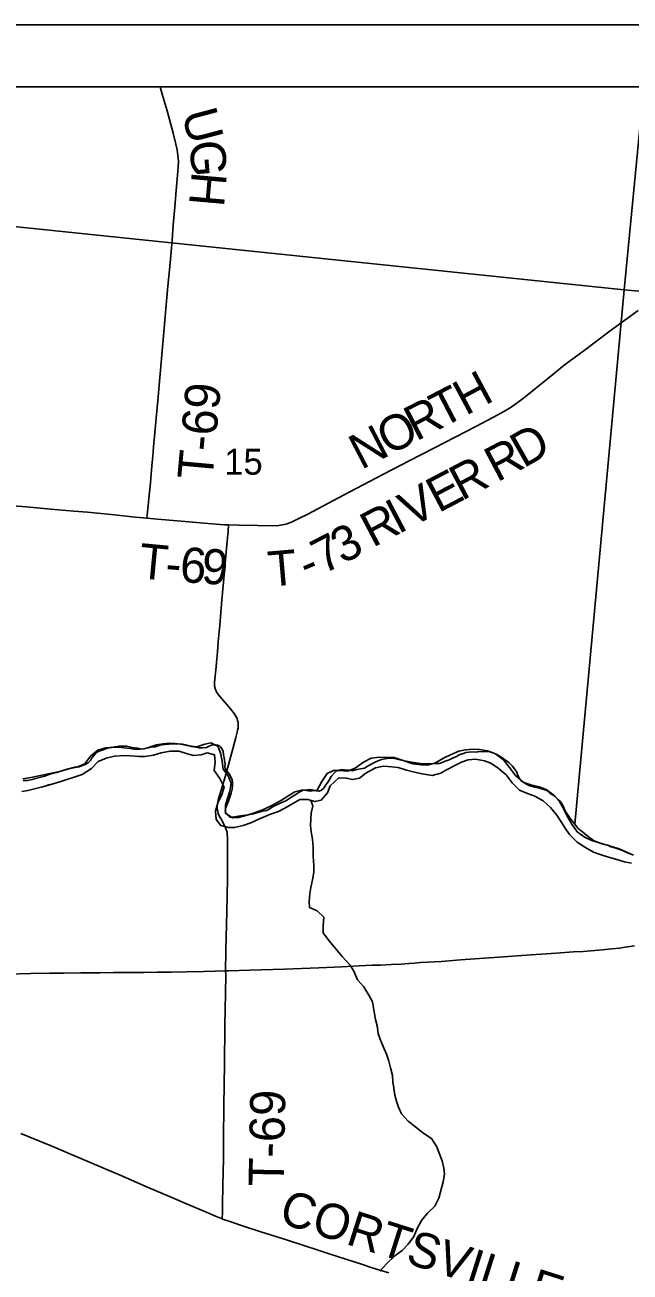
# Model space of a CAD drawing. Extents: x -19.5 to 44.1, y 0 to 22.
# Drawn here: x -15.704 to -14.727, y 7.445 to 9.461 of the extents above; entities that cross this region are included whole.
import ezdxf

# ---------------------------------------------------------------- set-up
doc = ezdxf.new("R2010")
doc.units = 0
for name, color, linetype in [('GM_X_Major_River', 7, 'Continuous'), ('GM_X_Minor_River', 7, 'Continuous'), ('GM_X_Section', 7, 'Continuous'), ('GM_X_Section_Text', 7, 'Continuous'), ('GM_X_Township_Road', 7, 'Continuous'), ('GM_X_Township_Road_Text', 7, 'Continuous'), ('SH_Data', 7, 'Continuous')]:
    doc.layers.add(name, color=color, linetype=linetype)

msp = doc.modelspace()

# ---------------------------------------------------------------- linework, layer by layer
at = {"layer": 'GM_X_Major_River'}
for points in [[(-14.7209, 8.1187), (-14.7337, 8.1239), (-14.7442, 8.1287), (-14.7597, 8.1339), (-14.7729, 8.1376), (-14.7884, 8.1425), (-14.7993, 8.1472), (-14.812, 8.1566), (-14.8209, 8.1686), (-14.8282, 8.1816), (-14.8333, 8.192), (-14.8407, 8.2054), (-14.8496, 8.2155), (-14.8623, 8.2249), (-14.8733, 8.2289), (-14.8872, 8.2322), (-14.8993, 8.2366), (-14.9116, 8.2475), (-14.9212, 8.2602), (-14.9313, 8.2726), (-14.9443, 8.2827), (-14.9572, 8.2875), (-14.97, 8.2893), (-14.9803, 8.2899), (-14.9924, 8.289), (-15.0031, 8.2869), (-15.0157, 8.2814), (-15.028, 8.2752), (-15.041, 8.2679), (-15.054, 8.2643), (-15.0642, 8.2645), (-15.0775, 8.2663), (-15.0933, 8.2719), (-15.1076, 8.2764), (-15.1319, 8.2769), (-15.1452, 8.2756), (-15.1575, 8.269), (-15.171, 8.2594), (-15.1832, 8.2543), (-15.1965, 8.2553), (-15.206, 8.2555), (-15.2159, 8.2508), (-15.2245, 8.2376), (-15.232, 8.2237), (-15.2442, 8.2221), (-15.2555, 8.2242), (-15.2681, 8.221), (-15.2781, 8.2151), (-15.29, 8.2078), (-15.3042, 8.1993), (-15.3191, 8.1927), (-15.3336, 8.1873), (-15.3451, 8.1834), (-15.3592, 8.1795), (-15.3691, 8.1789), (-15.3803, 8.1863), (-15.3804, 8.2), (-15.3764, 8.2121), (-15.3732, 8.2223), (-15.3711, 8.2348), (-15.3765, 8.2482), (-15.3843, 8.2579), (-15.3859, 8.2701), (-15.3876, 8.2819), (-15.3923, 8.2941), (-15.404, 8.3001), (-15.4135, 8.298), (-15.4265, 8.294), (-15.4394, 8.2954), (-15.4526, 8.2983), (-15.4621, 8.2993), (-15.4715, 8.2995), (-15.4818, 8.2985), (-15.4917, 8.2968), (-15.5016, 8.294), (-15.5119, 8.2904), (-15.5245, 8.2895), (-15.5343, 8.2912), (-15.5487, 8.2926), (-15.5608, 8.2932), (-15.5734, 8.2923), (-15.5867, 8.2884), (-15.5983, 8.2788), (-15.6073, 8.2664), (-15.6203, 8.261), (-15.6347, 8.2582), (-15.6466, 8.2546), (-15.6561, 8.2525), (-15.6687, 8.2498), (-15.6946, 8.2442), (-15.7079, 8.2422)], [(-14.7245, 8.1055), (-14.7355, 8.108), (-14.7483, 8.1117), (-14.7616, 8.1153), (-14.7732, 8.1194), (-14.7857, 8.1234), (-14.8, 8.1313), (-14.8123, 8.1399), (-14.8246, 8.1519), (-14.8316, 8.1623), (-14.8379, 8.1727), (-14.8449, 8.1831), (-14.8553, 8.1958), (-14.8668, 8.2067), (-14.8804, 8.2142), (-14.8921, 8.2182), (-14.9052, 8.2238), (-14.9171, 8.2358), (-14.9268, 8.2485), (-14.9395, 8.2594), (-14.9518, 8.2673), (-14.962, 8.2713), (-14.9764, 8.2738), (-14.9882, 8.2729), (-14.9989, 8.2689), (-15.0088, 8.2642), (-15.023, 8.2565), (-15.0326, 8.251), (-15.0463, 8.2475), (-15.0626, 8.25), (-15.0747, 8.2526), (-15.0879, 8.2562), (-15.1015, 8.2603), (-15.1117, 8.2617), (-15.125, 8.2623), (-15.1379, 8.2599), (-15.1533, 8.2514), (-15.1637, 8.2433), (-15.1751, 8.2408), (-15.1853, 8.2433), (-15.1974, 8.2439), (-15.211, 8.2305), (-15.2157, 8.2196), (-15.2258, 8.2076), (-15.2358, 8.2052), (-15.2474, 8.2088), (-15.26, 8.2087), (-15.273, 8.201), (-15.2853, 8.194), (-15.2949, 8.1892), (-15.3075, 8.1849), (-15.3266, 8.1769), (-15.3392, 8.1711), (-15.3515, 8.1664), (-15.3656, 8.1636), (-15.3755, 8.1631), (-15.3879, 8.1667), (-15.3953, 8.1764), (-15.3966, 8.1897), (-15.3925, 8.2033), (-15.3862, 8.2169), (-15.3826, 8.2286), (-15.3895, 8.2424), (-15.3984, 8.2555), (-15.397, 8.2691), (-15.3979, 8.2809), (-15.41, 8.2842), (-15.4195, 8.2806), (-15.4321, 8.2797), (-15.4419, 8.2822), (-15.4558, 8.2866), (-15.4699, 8.2869), (-15.484, 8.2841), (-15.4966, 8.2802), (-15.5103, 8.2782), (-15.5198, 8.2784), (-15.5338, 8.2794), (-15.544, 8.28), (-15.5596, 8.2788), (-15.5733, 8.2752), (-15.586, 8.2698), (-15.5968, 8.2586), (-15.6118, 8.249), (-15.6263, 8.244), (-15.6366, 8.2411), (-15.6465, 8.2375), (-15.6626, 8.2329), (-15.6759, 8.229), (-15.6866, 8.2262), (-15.6996, 8.223), (-15.7095, 8.2213)]]:
    msp.add_lwpolyline(points, dxfattribs=at)
at = {"layer": 'GM_X_Minor_River'}
for points in [[(-15.6682, 8.2316), (-15.6642, 8.2327)], [(-15.2422, 8.2072), (-15.2394, 8.1986), (-15.2418, 8.1865), (-15.2426, 8.1766), (-15.2431, 8.1664), (-15.2421, 8.1565), (-15.2395, 8.1443), (-15.2385, 8.1318), (-15.2387, 8.117), (-15.2377, 8.1018), (-15.2378, 8.0911), (-15.2398, 8.0786), (-15.2422, 8.0661), (-15.2438, 8.0566), (-15.2451, 8.0437), (-15.2444, 8.0342), (-15.232, 8.0288), (-15.2215, 8.0184), (-15.2224, 8.0048), (-15.2225, 7.993), (-15.2131, 7.9808), (-15.2023, 7.967), (-15.1918, 7.9547), (-15.179, 7.9409), (-15.1731, 7.931), (-15.1668, 7.9169), (-15.157, 7.9058), (-15.1485, 7.8924), (-15.1429, 7.8813), (-15.1407, 7.8684), (-15.1379, 7.8528), (-15.1353, 7.8426), (-15.1335, 7.8304), (-15.1299, 7.8197), (-15.1258, 7.809), (-15.1202, 7.7968), (-15.1166, 7.7854), (-15.1136, 7.7748), (-15.1107, 7.7626), (-15.1097, 7.7519), (-15.1083, 7.7417), (-15.1065, 7.7307), (-15.1039, 7.7208), (-15.1006, 7.7112), (-15.0958, 7.7002), (-15.0853, 7.6883), (-15.0729, 7.6787), (-15.0616, 7.6698), (-15.0473, 7.6606), (-15.0388, 7.6468), (-15.0351, 7.6369), (-15.0303, 7.6244), (-15.0274, 7.6126), (-15.0263, 7.6027), (-15.0287, 7.5906), (-15.0358, 7.5641), (-15.0423, 7.5512), (-15.0538, 7.5396), (-15.0634, 7.5279), (-15.0707, 7.5151), (-15.0762, 7.5022), (-15.085, 7.4898), (-15.0946, 7.4796), (-15.1068, 7.4707), (-15.1201, 7.4579), (-15.1309, 7.4459)]]:
    msp.add_lwpolyline(points, dxfattribs=at)
at = {"layer": 'GM_X_Section'}
msp.add_line((-14.7042, 9.3611), (-15.7271, 9.3611), dxfattribs=at)
for points in [[(-15.7271, 9.3611), (-15.7488, 9.138), (-14.7362, 9.0329), (-14.7042, 9.3611)], [(-14.7042, 9.3611), (-14.7362, 9.0329), (-13.8609, 8.9536)], [(-15.7488, 9.138), (-14.7362, 9.0329), (-14.8161, 8.169), (-14.8235, 8.1779), (-14.8287, 8.1859), (-14.8317, 8.1905), (-14.8342, 8.1966), (-14.8368, 8.2015), (-14.839, 8.2053), (-14.8439, 8.2092), (-14.8484, 8.2142), (-14.8555, 8.2185), (-14.8611, 8.2231), (-14.8675, 8.2251), (-14.8732, 8.2267), (-14.8807, 8.2287), (-14.8902, 8.2315), (-14.8969, 8.2353), (-14.9022, 8.2381), (-14.9051, 8.2427), (-14.9081, 8.2473), (-14.9096, 8.2526), (-14.9133, 8.2583), (-14.917, 8.2633), (-14.9226, 8.2683), (-14.9278, 8.2722), (-14.9353, 8.2776), (-14.9432, 8.2818), (-14.9496, 8.2846), (-14.9556, 8.2862), (-14.9636, 8.2859), (-14.9712, 8.286), (-14.975, 8.2853), (-14.9803, 8.2858), (-14.9871, 8.2851), (-14.992, 8.2844), (-14.9958, 8.283), (-15.0019, 8.2812), (-15.0073, 8.2782), (-15.0134, 8.2753), (-15.0191, 8.2727), (-15.0256, 8.2705), (-15.0305, 8.2687), (-15.0347, 8.2669), (-15.0419, 8.2666), (-15.0491, 8.2663), (-15.0623, 8.2665), (-15.0797, 8.2691), (-15.0963, 8.2723), (-15.105, 8.2743), (-15.1099, 8.2752), (-15.1152, 8.2756), (-15.1228, 8.2746), (-15.1285, 8.2732), (-15.1361, 8.2702), (-15.143, 8.2666), (-15.1499, 8.2629), (-15.1556, 8.2595), (-15.1624, 8.2581), (-15.1704, 8.2564), (-15.1757, 8.2549), (-15.1818, 8.2558), (-15.1878, 8.2566), (-15.1943, 8.2567), (-15.2, 8.2553), (-15.2046, 8.2512), (-15.2096, 8.2459), (-15.2127, 8.2399), (-15.2158, 8.235), (-15.2181, 8.2324), (-15.2197, 8.2298), (-15.222, 8.2264), (-15.2254, 8.2238), (-15.2292, 8.222), (-15.2334, 8.2228), (-15.2383, 8.2236), (-15.2425, 8.2248), (-15.2485, 8.2245), (-15.2546, 8.2235), (-15.2611, 8.2206), (-15.2668, 8.2169), (-15.2733, 8.2132), (-15.2783, 8.2091), (-15.284, 8.2061), (-15.2909, 8.2032), (-15.2974, 8.1999), (-15.3042, 8.1966), (-15.3099, 8.1932), (-15.3138, 8.191), (-15.3206, 8.1896), (-15.3278, 8.1874), (-15.3351, 8.1856), (-15.3438, 8.1839), (-15.3518, 8.1829), (-15.3597, 8.1818), (-15.3658, 8.1804), (-15.3707, 8.1801), (-15.3734, 8.1801), (-15.3767, 8.1832), (-15.3805, 8.1874), (-15.3808, 8.1909), (-15.3804, 8.1943), (-15.378, 8.1995), (-15.3757, 8.2059), (-15.3741, 8.2108), (-15.3713, 8.2191), (-15.3697, 8.2252), (-15.3692, 8.2305), (-15.3692, 8.2361), (-15.3695, 8.2407), (-15.372, 8.246), (-15.3739, 8.2495), (-15.3765, 8.2529), (-15.3791, 8.2563), (-15.3809, 8.259), (-15.3813, 8.2617), (-15.3808, 8.2662), (-15.3819, 8.2715), (-15.3822, 8.2768), (-15.3837, 8.281), (-15.3843, 8.2867), (-15.3862, 8.2905), (-15.3879, 8.2935), (-15.3903, 8.2959), (-15.3929, 8.2967), (-15.3967, 8.2971), (-15.4016, 8.2968), (-15.4066, 8.2946), (-15.4108, 8.2928), (-15.4172, 8.2921), (-15.4236, 8.2922), (-15.4278, 8.293), (-15.435, 8.2943), (-15.4425, 8.2967), (-15.4497, 8.2979), (-15.4614, 8.2984), (-15.472, 8.2982), (-15.4838, 8.2969), (-15.4895, 8.2954), (-15.4937, 8.294), (-15.4994, 8.2937), (-15.5051, 8.2919), (-15.5104, 8.2912), (-15.5157, 8.2901), (-15.5217, 8.2917), (-15.5312, 8.2926), (-15.5399, 8.2947), (-15.552, 8.2948), (-15.5618, 8.2935), (-15.5732, 8.291), (-15.579, 8.2884), (-15.5847, 8.287), (-15.5896, 8.2833), (-15.5931, 8.2799), (-15.5962, 8.2758), (-15.5985, 8.2716), (-15.602, 8.2679), (-15.6058, 8.2657), (-15.6127, 8.2628), (-15.6168, 8.2617), (-15.6241, 8.2607), (-15.632, 8.2589), (-15.6389, 8.2567), (-15.6465, 8.2545), (-15.653, 8.2524), (-15.6583, 8.2513), (-15.6659, 8.2488), (-15.6724, 8.2466), (-15.6788, 8.2448), (-15.6849, 8.243), (-15.6925, 8.2412), (-15.6997, 8.2394), (-15.7073, 8.2395)], [(-14.724, 8.1196), (-14.7335, 8.1233), (-14.7372, 8.1255), (-14.7447, 8.1282), (-14.753, 8.131), (-14.7579, 8.1322), (-14.7628, 8.1349), (-14.7677, 8.1361), (-14.7737, 8.1377), (-14.7794, 8.1397), (-14.7858, 8.1425), (-14.7899, 8.1456), (-14.7967, 8.1506), (-14.803, 8.156), (-14.8109, 8.1621), (-14.8161, 8.169), (-14.7362, 9.0329), (-13.8609, 8.9536)]]:
    msp.add_lwpolyline(points, dxfattribs=at)
at = {"layer": 'GM_X_Township_Road'}
for points in [[(-15.5072, 8.6634), (-15.5067, 8.6678), (-15.504, 8.6956), (-15.5017, 8.7204), (-15.4991, 8.7482), (-15.4978, 8.7636), (-15.4964, 8.7791), (-15.4891, 8.8596), (-15.487, 8.8843), (-15.4842, 8.9153), (-15.4804, 8.9586), (-15.4776, 8.9895), (-15.474, 9.0329), (-15.4699, 9.0764), (-15.4687, 9.0885), (-15.4667, 9.1132), (-15.4646, 9.1378), (-15.4619, 9.1666), (-15.4598, 9.1937), (-15.4576, 9.2183), (-15.4567, 9.231), (-15.4563, 9.2404), (-15.4571, 9.2497), (-15.4584, 9.259), (-15.4603, 9.2682), (-15.4649, 9.2863), (-15.4748, 9.3223), (-15.4824, 9.3492), (-15.4858, 9.3611)], [(-15.3753, 8.6525), (-15.3587, 8.6522), (-15.3285, 8.6515), (-15.3039, 8.6512), (-15.2939, 8.6519), (-15.2886, 8.6527), (-15.2825, 8.654), (-15.2795, 8.6547), (-15.2738, 8.6571), (-15.2627, 8.6623), (-15.2461, 8.6708), (-15.2321, 8.6781), (-15.1804, 8.7055), (-15.1252, 8.7347), (-15.0838, 8.7562), (-15.0424, 8.7774), (-14.9758, 8.8119), (-14.9484, 8.8264), (-14.9294, 8.8368), (-14.9188, 8.8432), (-14.9111, 8.8485), (-14.8987, 8.8578), (-14.8575, 8.8908), (-14.8329, 8.9107), (-14.8009, 8.9345), (-14.7586, 8.9662), (-14.7135, 8.9993)], [(-15.7234, 8.6833), (-15.7026, 8.6816), (-15.6624, 8.6779), (-15.6252, 8.675), (-15.6031, 8.673), (-15.5815, 8.6709), (-15.5652, 8.6693), (-15.5497, 8.6676), (-15.5262, 8.6653), (-15.5191, 8.6646), (-15.5072, 8.6634)], [(-15.3753, 8.6525), (-15.382, 8.653), (-15.4026, 8.6542), (-15.4332, 8.6571), (-15.4582, 8.6594), (-15.4903, 8.662), (-15.5072, 8.6634)], [(-15.3801, 7.9315), (-15.3802, 7.9386), (-15.3801, 7.945), (-15.38, 7.9492), (-15.3795, 7.9659), (-15.3785, 8.0062), (-15.3776, 8.0514), (-15.3776, 8.0544), (-15.3773, 8.0805), (-15.3771, 8.0932), (-15.3769, 8.1272), (-15.377, 8.1459), (-15.3774, 8.1521), (-15.3778, 8.1553), (-15.3786, 8.1584), (-15.3796, 8.1614), (-15.3808, 8.1643), (-15.3881, 8.178), (-15.391, 8.1834), (-15.392, 8.1862), (-15.3928, 8.1891), (-15.3934, 8.1921), (-15.3937, 8.195), (-15.3936, 8.1987), (-15.3933, 8.2016), (-15.3928, 8.2045), (-15.3922, 8.2076), (-15.3905, 8.2135), (-15.3867, 8.2252), (-15.3797, 8.2491), (-15.3687, 8.2908), (-15.3638, 8.309), (-15.3617, 8.3175), (-15.3608, 8.3207), (-15.36, 8.3241), (-15.3596, 8.3272), (-15.3596, 8.3304), (-15.36, 8.3335), (-15.3607, 8.3366), (-15.3617, 8.3396), (-15.363, 8.3425), (-15.3646, 8.3452), (-15.3663, 8.3478), (-15.3721, 8.3552), (-15.3883, 8.374), (-15.3914, 8.3781), (-15.3939, 8.3813), (-15.3946, 8.3825), (-15.3954, 8.3839), (-15.396, 8.3852), (-15.3965, 8.3866), (-15.3969, 8.388), (-15.3973, 8.3895), (-15.3976, 8.3908), (-15.3979, 8.3925), (-15.398, 8.3939), (-15.398, 8.3954), (-15.3978, 8.3985), (-15.3956, 8.4233), (-15.3949, 8.4303), (-15.3934, 8.4476), (-15.392, 8.4635), (-15.3894, 8.4907), (-15.386, 8.5313), (-15.3819, 8.5772), (-15.3786, 8.6148), (-15.3759, 8.6425), (-15.3753, 8.6525)], [(-15.3801, 7.9315), (-15.3752, 7.9317), (-15.3411, 7.9328), (-15.3039, 7.9339), (-15.2852, 7.9344), (-15.2573, 7.9352), (-15.2294, 7.9363), (-15.1922, 7.9381), (-15.1643, 7.9399), (-15.1429, 7.9406), (-15.1301, 7.941), (-15.112, 7.9419), (-15.0964, 7.9426), (-15.084, 7.9433), (-15.0747, 7.9441), (-15.0654, 7.9448), (-15.0315, 7.9469), (-15.0253, 7.9474), (-15.0006, 7.9493), (-14.9541, 7.9526), (-14.9385, 7.9538), (-14.9015, 7.9563), (-14.8862, 7.9572), (-14.8458, 7.9599), (-14.8179, 7.9621), (-14.8024, 7.9631), (-14.7838, 7.9644), (-14.7715, 7.9653), (-14.756, 7.9669), (-14.7437, 7.9685), (-14.7346, 7.9699), (-14.7195, 7.9722)], [(-15.7322, 7.9264), (-15.695, 7.9271), (-15.6639, 7.9279), (-15.6422, 7.928), (-15.6142, 7.9281), (-15.5832, 7.9285), (-15.5615, 7.9288), (-15.549, 7.9289), (-15.5304, 7.929), (-15.5118, 7.9291), (-15.4901, 7.9293), (-15.4683, 7.9296), (-15.4435, 7.9298), (-15.4156, 7.9304), (-15.397, 7.9309), (-15.3801, 7.9315)], [(-15.3857, 7.5305), (-15.3855, 7.534), (-15.3853, 7.5381), (-15.3849, 7.5535), (-15.3845, 7.5846), (-15.3837, 7.6283), (-15.3833, 7.6624), (-15.3828, 7.7117), (-15.3822, 7.7487), (-15.3818, 7.7797), (-15.3812, 7.8424), (-15.3807, 7.87), (-15.3803, 7.8946), (-15.38, 7.9259), (-15.3801, 7.9315)], [(-15.3857, 7.5305), (-15.3966, 7.5348), (-15.4166, 7.5433), (-15.4394, 7.5532), (-15.4708, 7.5667), (-15.505, 7.5814), (-15.5506, 7.6011), (-15.5963, 7.6205), (-15.6392, 7.6387), (-15.662, 7.6485), (-15.682, 7.6569), (-15.6964, 7.6628), (-15.7109, 7.6687)], [(-15.1164, 7.4431), (-15.1431, 7.4515), (-15.1608, 7.4571), (-15.1726, 7.4609), (-15.1991, 7.4694), (-15.211, 7.4732), (-15.2287, 7.4791), (-15.2818, 7.4964), (-15.3232, 7.5097), (-15.3497, 7.5183), (-15.3734, 7.526), (-15.3851, 7.5302), (-15.3857, 7.5305)]]:
    msp.add_lwpolyline(points, dxfattribs=at)
at = {"layer": 'SH_Data'}
for p, q in [((-19.48, 9.4611), (-12.48, 9.4611)), ((-16.9061, 9.3611), (-12.58, 9.3611))]:
    msp.add_line(p, q, dxfattribs=at)

# ---------------------------------------------------------------- texts
at = {"layer": 'GM_X_Section_Text'}
msp.add_text('15', height=0.04186, rotation=0, dxfattribs=at).set_placement((-15.3824, 8.7339))
at = {"layer": 'GM_X_Township_Road_Text'}
for s, height, rotation, p in [('U', 0.0568, 284.9216, (-15.4514, 9.318)), ('G', 0.0568, 275.0188, (-15.4389, 9.2723)), ('H', 0.0568, 264.9518, (-15.4346, 9.2251)), ('H', 0.0568, 28.1832, (-14.9923, 8.8286)), ('T-69', 0.05682, 84.7682, (-15.4016, 8.7241)), ('T', 0.0568, 27.419, (-15.0307, 8.8087)), ('R', 0.0568, 27.4046, (-15.0722, 8.7872)), ('O', 0.0568, 27.4073, (-15.1166, 8.7642)), ('N', 0.0568, 27.4073, (-15.161, 8.7412)), ('D', 0.0568, 29.715, (-14.8987, 8.7437)), ('R', 0.0568, 27.8575, (-14.9417, 8.721)), ('R', 0.0568, 27.7435, (-14.9986, 8.691)), ('E', 0.0568, 27.7323, (-15.0362, 8.6713)), ('V', 0.0568, 27.7348, (-15.0805, 8.648)), ('I', 0.0568, 27.7345, (-15.1012, 8.6371)), ('R', 0.0568, 27.7364, (-15.1425, 8.6154)), ('3', 0.0568, 27.92, (-15.1909, 8.5886)), ('7', 0.0568, 27.3981, (-15.2225, 8.5722)), ('T', 0.0568, 354.5858, (-15.5221, 8.5667)), ('6', 0.0568, 355.7696, (-15.4553, 8.5607)), ('9', 0.0568, 355.8214, (-15.4203, 8.5582)), ('T', 0.0568, 4.969, (-15.3094, 8.5527)), ('-', 0.0568, 22.9429, (-15.2483, 8.5611)), ('-', 0.0568, 355.5815, (-15.4787, 8.5626)), ('T-69', 0.05682, 88.9468, (-15.2863, 7.5825)), ('CORTSVILLE', 0.05682, 342.3356, (-15.2963, 7.525))]:
    msp.add_text(s, height=height, rotation=rotation, dxfattribs=at).set_placement(p)

doc.saveas('drawing.dxf')
